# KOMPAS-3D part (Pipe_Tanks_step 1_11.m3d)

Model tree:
1. X Axis
2. Y Axis
3. Z Axis  (labels: Bend 90 Dn 50; Pipe Dn 50; C:\Program Files\ASCON\KOMPAS-3D V10\Sys\graphic.lyt; Pipe_Tanks_step 1_11.m3d)
     Òîëùèíà ñòåíêè 1 = 1

Referenced files in C:\Documents and Settings\kashirsky\Мои документы\Camtasia Studio\Pipelines3D\Tanks\: Tanks_step 1.a3d, Tanks_step 1.spw
Referenced files in C:\Documents and Settings\kashirsky\Мои документы\Camtasia Studio\Pipelines3D\Tanks\Tanks_step 1_Pipes\: Pipe_Tanks_step 1_11.m3d
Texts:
  Pipe Dn 50
  Steel ASTM A295
  Three Point Plane
  Plane at Angle
  Line and Point Plane
  Axis through Two Vertices
  Axis of Feature
  Axis of Conical Surface
  Axis through Edge
  Trim by Surface
  Trim by Sketch
  Feature with No History
  Intersection Axis of Two Planes
  Two Line Plane
  Line and Face Plane
  Bend by line
  Hole in sheet body
  Cut in sheet body
  Point in CM
  Linear Dimension from Line to Point
  Surface Finish Symbol
  Geometric Tolerance Symbol
  Leader #1
  Leader #2
  Leader #3
  Shape Deviations and Datum
  Node point number
  Mark of coordination axis
  Node point designation
  Mark/Reference designation with leader
  Mark/reference designation on line
  Mark/Reference designation without leader
  Bend 90 Dn 50
  Plane of section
